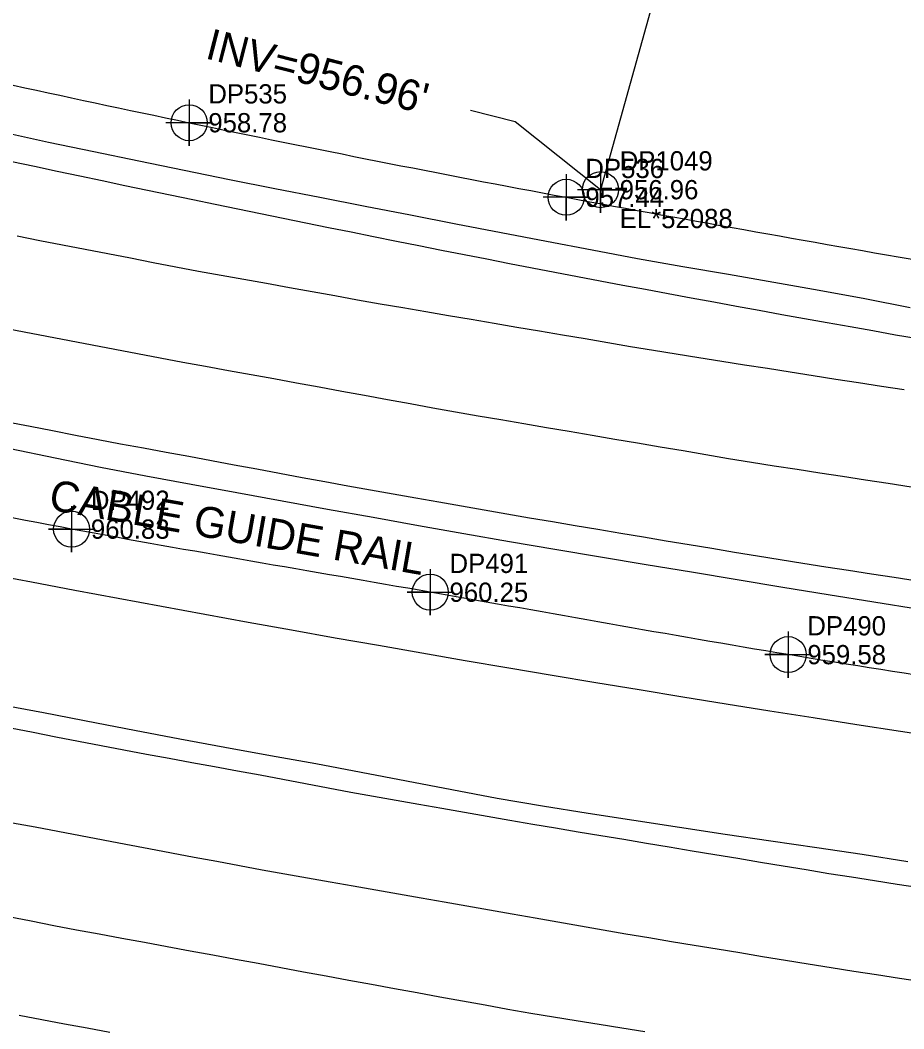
# Model space of a CAD drawing. Extents: x 1182322 to 1186765, y 572295 to 575411.
# Drawn here: x 1185843 to 1185957.8, y 573689.5 to 573820.6 of the extents above; entities that cross this region are included whole.
import ezdxf

# ---------------------------------------------------------------- set-up
doc = ezdxf.new("R2010")
doc.units = 0
for name, color, linetype in [('COGO Default Chain', 7, 'Continuous'), ('Exist Guardrail', 7, 'Continuous'), ('Exist Guardrail Cable Guide Rail', 7, 'Continuous'), ('Exist Guardrail Cable Guide Rail Cogo Elevation', 7, 'Continuous'), ('Exist Guardrail Cable Guide Rail Cogo Number', 7, 'Continuous'), ('Exist Guardrail Cable Guide Rail Cogo Point CELL', 7, 'Continuous'), ('Exist Guardrail Cable Guide Rail Text', 7, 'Continuous'), ('Exist Guardrail Cogo Elevation', 7, 'Continuous'), ('Exist Guardrail Cogo Number', 7, 'Continuous'), ('Exist Guardrail Cogo Point CELL', 7, 'Continuous'), ('Exist Horizontal Alignment', 7, 'Continuous'), ('Exist Roads EOP', 7, 'Continuous'), ('Exist Roads EOT', 7, 'Continuous'), ('Exist Structure Minor Pipes CMP 8 Inch', 7, 'Continuous'), ('Exist Structure Minor Pipes CMP 8 Inch Cogo Comment', 7, 'Continuous'), ('Exist Structure Minor Pipes CMP 8 Inch Cogo Elevation', 7, 'Continuous'), ('Exist Structure Minor Pipes CMP 8 Inch Cogo Number', 7, 'Continuous'), ('Exist Structure Minor Pipes CMP 8 Inch Cogo Point CELL', 7, 'Continuous'), ('Exist Structure Minor Pipes CMP 8 Inch Invert', 7, 'Continuous'), ('Exist Structure Minor Pipes CMP 8 Inch Leader', 7, 'Continuous')]:
    doc.layers.add(name, color=color, linetype=linetype)

msp = doc.modelspace()

# ---------------------------------------------------------------- linework, layer by layer
at = {"layer": 'COGO Default Chain'}
msp.add_arc((1186442.72, 576894.22), 3203, 256.26372, 262.82154, dxfattribs=at)
at = {"layer": 'Exist Guardrail'}
for points in [[(1185390.3, 573940.07), (1185437.01, 573922.28), (1185484.33, 573906.54), (1185526.22, 573893.43), (1185574.13, 573879.46), (1185622.33, 573866.54), (1185670.88, 573853.88), (1185719.13, 573841.46), (1185767.43, 573829.33), (1185816.18, 573817.9), (1185864.94, 573807.26), (1185913.93, 573797.57), (1185963.25, 573788.74), (1186012.41, 573780.34), (1186049.41, 573774.82)], [(1186024.1, 573651.4), (1185974.53, 573658.23), (1185925.08, 573665.96), (1185876.03, 573674.4), (1185826.75, 573683.69), (1185777.99, 573693.31), (1185734.89, 573702.52), (1185686.39, 573713.51)]]:
    msp.add_spline(points, degree=3, dxfattribs=at)
at = {"layer": 'Exist Guardrail Cable Guide Rail'}
msp.add_spline([(1186038.69, 573724.46), (1185991.11, 573730.82), (1185942.77, 573738.14), (1185896.28, 573746.25), (1185849.68, 573754.45), (1185801.69, 573764.04), (1185755.31, 573774.06), (1185708.64, 573784.68), (1185661.69, 573796.05), (1185615.35, 573807.21)], degree=3, dxfattribs=at)
at = {"layer": 'Exist Guardrail Cable Guide Rail Cogo Point CELL'}
for points in [[(1185849.68, 573757.45), (1185849.68, 573751.45), (1185849.68, 573754.45), (1185846.68, 573754.45), (1185852.68, 573754.45)], [(1185896.28, 573749.25), (1185896.28, 573743.25), (1185896.28, 573746.25), (1185893.28, 573746.25), (1185899.28, 573746.25)], [(1185942.77, 573741.14), (1185942.77, 573735.14), (1185942.77, 573738.14), (1185939.77, 573738.14), (1185945.77, 573738.14)]]:
    msp.add_lwpolyline(points, dxfattribs=at)
for centre in [(1185849.68, 573754.45), (1185896.28, 573746.25), (1185942.77, 573738.14)]:
    msp.add_circle(centre, 2.34, dxfattribs=at)
at = {"layer": 'Exist Guardrail Cogo Point CELL'}
for points in [[(1185864.94, 573810.26), (1185864.94, 573804.26), (1185864.94, 573807.26), (1185867.94, 573807.26), (1185861.94, 573807.26)], [(1185913.93, 573800.57), (1185913.93, 573794.57), (1185913.93, 573797.57), (1185916.93, 573797.57), (1185910.93, 573797.57)]]:
    msp.add_lwpolyline(points, dxfattribs=at)
for centre in [(1185864.94, 573807.26), (1185913.93, 573797.57)]:
    msp.add_circle(centre, 2.34, dxfattribs=at)
at = {"layer": 'Exist Horizontal Alignment'}
msp.add_arc((1186442.72, 576894.22), 3203, 256.26372, 262.82154, dxfattribs=at)
at = {"layer": 'Exist Roads EOP'}
for points in [[(1185840.82, 573806.03), (1185846.68, 573804.73), (1185852.55, 573803.51), (1185858.43, 573802.29), (1185864.3, 573801.08), (1185870.18, 573799.86), (1185876.06, 573798.71), (1185881.95, 573797.57), (1185887.84, 573796.42), (1185893.73, 573795.28), (1185899.62, 573794.14), (1185905.51, 573793), (1185911.4, 573791.87), (1185917.3, 573790.74), (1185923.19, 573789.62), (1185929.1, 573788.58), (1185935.01, 573787.56), (1185940.92, 573786.53), (1185946.83, 573785.51), (1185952.73, 573784.42), (1185958.62, 573783.27)], [(1185959.84, 573744.02), (1185953.91, 573744.97), (1185947.99, 573745.92), (1185942.07, 573746.88), (1185936.15, 573747.85), (1185930.23, 573748.84), (1185924.31, 573749.82), (1185918.39, 573750.81), (1185912.48, 573751.79), (1185906.56, 573752.79), (1185900.65, 573753.83), (1185894.75, 573754.89), (1185888.84, 573755.94), (1185882.93, 573757), (1185877.03, 573758.07), (1185871.13, 573759.16), (1185865.23, 573760.25), (1185859.33, 573761.34), (1185853.44, 573762.46), (1185847.56, 573763.67), (1185841.69, 573764.88)], [(1185840.13, 573731.72), (1185846.04, 573730.64), (1185852.92, 573729.28), (1185857.84, 573728.33), (1185863.74, 573727.18), (1185869.59, 573726.12), (1185875.5, 573725.05), (1185881.4, 573723.98), (1185887.3, 573722.88), (1185893.19, 573721.76), (1185899.08, 573720.63), (1185904.98, 573719.51), (1185910.87, 573718.49), (1185916.81, 573717.56), (1185922.72, 573716.63), (1185928.65, 573715.7), (1185934.59, 573714.8), (1185940.54, 573713.95), (1185946.49, 573713.09), (1185952.38, 573712.21), (1185958.32, 573711.24)]]:
    msp.add_lwpolyline(points, dxfattribs=at)
at = {"layer": 'Exist Roads EOT'}
for points in [[(1185841.93, 573802.24), (1185844.86, 573801.61), (1185847.79, 573800.98), (1185850.73, 573800.35), (1185853.66, 573799.74), (1185856.6, 573799.12), (1185859.54, 573798.5), (1185862.47, 573797.89), (1185865.41, 573797.29), (1185868.35, 573796.68), (1185871.29, 573796.07), (1185874.23, 573795.47), (1185877.16, 573794.86), (1185880.1, 573794.26), (1185883.04, 573793.66), (1185885.98, 573793.07), (1185888.92, 573792.47), (1185891.87, 573791.88), (1185894.81, 573791.3), (1185897.75, 573790.71), (1185900.69, 573790.13), (1185903.64, 573789.56), (1185906.58, 573788.98), (1185909.53, 573788.41), (1185912.47, 573787.85), (1185915.42, 573787.29), (1185918.37, 573786.73), (1185921.32, 573786.17), (1185924.26, 573785.62), (1185927.21, 573785.06), (1185930.16, 573784.51), (1185933.11, 573783.97), (1185936.06, 573783.43), (1185939.02, 573782.9), (1185941.97, 573782.36), (1185944.92, 573781.83), (1185947.87, 573781.3), (1185950.83, 573780.77), (1185953.78, 573780.24), (1185956.73, 573779.71), (1185959.69, 573779.2)], [(1185842.59, 573792.54), (1185845.54, 573791.97), (1185848.48, 573791.4), (1185851.43, 573790.83), (1185854.37, 573790.26), (1185857.32, 573789.69), (1185860.26, 573789.11), (1185863.21, 573788.55), (1185866.16, 573787.99), (1185869.11, 573787.45), (1185872.06, 573786.92), (1185875.01, 573786.39), (1185877.97, 573785.86), (1185880.92, 573785.33), (1185883.87, 573784.8), (1185886.82, 573784.26), (1185889.78, 573783.74), (1185892.73, 573783.23), (1185895.69, 573782.72), (1185898.65, 573782.22), (1185901.61, 573781.72), (1185904.56, 573781.21), (1185907.52, 573780.71), (1185910.48, 573780.2), (1185913.44, 573779.7), (1185916.39, 573779.2), (1185919.35, 573778.69), (1185922.31, 573778.19), (1185925.27, 573777.7), (1185928.23, 573777.23), (1185931.19, 573776.76), (1185934.16, 573776.29), (1185937.12, 573775.82), (1185940.08, 573775.35), (1185943.05, 573774.88), (1185946.01, 573774.41), (1185948.97, 573773.94), (1185951.94, 573773.49), (1185954.9, 573773.04), (1185957.87, 573772.6)], [(1185958.76, 573759.91), (1185955.79, 573760.37), (1185952.82, 573760.82), (1185949.86, 573761.27), (1185946.89, 573761.73), (1185943.93, 573762.18), (1185940.96, 573762.63), (1185938, 573763.11), (1185935.04, 573763.6), (1185932.08, 573764.1), (1185929.13, 573764.61), (1185926.17, 573765.11), (1185923.21, 573765.61), (1185920.25, 573766.11), (1185917.3, 573766.62), (1185914.34, 573767.12), (1185911.38, 573767.62), (1185908.42, 573768.12), (1185905.46, 573768.63), (1185902.51, 573769.13), (1185899.55, 573769.65), (1185896.6, 573770.18), (1185893.65, 573770.72), (1185890.7, 573771.26), (1185887.75, 573771.8), (1185884.8, 573772.34), (1185881.84, 573772.88), (1185878.89, 573773.42), (1185875.94, 573773.96), (1185872.99, 573774.5), (1185870.04, 573775.04), (1185867.09, 573775.58), (1185864.14, 573776.12), (1185861.19, 573776.68), (1185858.24, 573777.24), (1185855.3, 573777.8), (1185852.35, 573778.37), (1185849.4, 573778.93), (1185846.46, 573779.5), (1185843.51, 573780.06), (1185840.57, 573780.62)], [(1185841.32, 573768.38), (1185844.27, 573767.82), (1185847.21, 573767.25), (1185850.16, 573766.68), (1185853.11, 573766.11), (1185856.05, 573765.55), (1185859, 573765.01), (1185861.95, 573764.46), (1185864.9, 573763.91), (1185867.85, 573763.36), (1185870.8, 573762.81), (1185873.75, 573762.27), (1185876.7, 573761.72), (1185879.65, 573761.17), (1185882.6, 573760.63), (1185885.55, 573760.09), (1185888.5, 573759.56), (1185891.46, 573759.03), (1185894.41, 573758.5), (1185897.37, 573757.98), (1185900.32, 573757.46), (1185903.27, 573756.94), (1185906.23, 573756.43), (1185909.19, 573755.93), (1185912.15, 573755.43), (1185915.1, 573754.93), (1185918.06, 573754.43), (1185921.02, 573753.93), (1185923.98, 573753.43), (1185926.94, 573752.94), (1185929.9, 573752.45), (1185932.86, 573751.96), (1185935.82, 573751.47), (1185938.78, 573750.99), (1185941.74, 573750.51), (1185944.7, 573750.04), (1185947.67, 573749.57), (1185950.63, 573749.11), (1185953.59, 573748.65), (1185956.56, 573748.19), (1185959.53, 573747.74)], [(1185841.73, 573728.62), (1185844.67, 573728.05), (1185847.62, 573727.48), (1185850.57, 573726.91), (1185853.51, 573726.34), (1185856.46, 573725.77), (1185859.41, 573725.22), (1185862.36, 573724.68), (1185865.31, 573724.14), (1185868.26, 573723.59), (1185871.21, 573723.05), (1185874.16, 573722.51), (1185877.11, 573721.96), (1185880.06, 573721.41), (1185883, 573720.85), (1185885.95, 573720.29), (1185888.9, 573719.74), (1185891.86, 573719.23), (1185894.81, 573718.71), (1185897.77, 573718.2), (1185900.72, 573717.68), (1185903.68, 573717.16), (1185906.63, 573716.64), (1185909.59, 573716.13), (1185912.55, 573715.63), (1185915.5, 573715.13), (1185918.46, 573714.63), (1185921.42, 573714.14), (1185924.38, 573713.65), (1185927.34, 573713.15), (1185930.3, 573712.66), (1185933.26, 573712.17), (1185936.22, 573711.68), (1185939.18, 573711.19), (1185942.14, 573710.7), (1185945.1, 573710.21), (1185948.06, 573709.72), (1185951.02, 573709.26), (1185953.99, 573708.8), (1185956.95, 573708.33), (1185959.91, 573707.87)], [(1185960.21, 573695.64), (1185957.24, 573696.07), (1185954.27, 573696.51), (1185951.31, 573696.97), (1185948.35, 573697.45), (1185945.39, 573697.93), (1185942.42, 573698.41), (1185939.46, 573698.89), (1185936.5, 573699.37), (1185933.54, 573699.86), (1185930.58, 573700.34), (1185927.62, 573700.83), (1185924.66, 573701.32), (1185921.7, 573701.82), (1185918.75, 573702.33), (1185915.79, 573702.85), (1185912.84, 573703.37), (1185909.89, 573703.9), (1185906.93, 573704.42), (1185903.98, 573704.94), (1185901.02, 573705.46), (1185898.07, 573705.98), (1185895.11, 573706.49), (1185892.16, 573707.01), (1185889.2, 573707.53), (1185886.25, 573708.04), (1185883.29, 573708.56), (1185880.34, 573709.08), (1185877.38, 573709.61), (1185874.43, 573710.14), (1185871.48, 573710.69), (1185868.53, 573711.25), (1185865.59, 573711.8), (1185862.64, 573712.36), (1185859.69, 573712.92), (1185856.74, 573713.47), (1185853.79, 573714.03), (1185850.85, 573714.58), (1185847.9, 573715.14), (1185844.95, 573715.7), (1185842, 573716.25)], [(1185841.48, 573704.1), (1185844.42, 573703.53), (1185847.37, 573702.96), (1185850.31, 573702.4), (1185853.26, 573701.85), (1185856.21, 573701.3), (1185859.16, 573700.76), (1185862.11, 573700.21), (1185865.06, 573699.66), (1185868.01, 573699.12), (1185870.96, 573698.57), (1185873.91, 573698.03), (1185876.86, 573697.48), (1185879.81, 573696.93), (1185882.76, 573696.39), (1185885.71, 573695.84), (1185888.66, 573695.3), (1185891.61, 573694.75), (1185894.56, 573694.22), (1185897.52, 573693.68), (1185900.47, 573693.15), (1185903.42, 573692.62), (1185906.37, 573692.08), (1185909.33, 573691.57), (1185912.29, 573691.09), (1185915.25, 573690.61), (1185918.21, 573690.13), (1185921.17, 573689.65), (1185924.14, 573689.17)], [(1185854.66, 573689.02), (1185851.71, 573689.58), (1185848.76, 573690.14), (1185845.81, 573690.7), (1185842.86, 573691.23)]]:
    msp.add_lwpolyline(points, dxfattribs=at)
at = {"layer": 'Exist Structure Minor Pipes CMP 8 Inch'}
msp.add_line((1185930.63, 573842.39), (1185918.39, 573798.56), dxfattribs=at)
at = {"layer": 'Exist Structure Minor Pipes CMP 8 Inch Cogo Point CELL'}
msp.add_lwpolyline([(1185918.39, 573801.56), (1185918.39, 573795.56), (1185918.39, 573798.56), (1185921.39, 573798.56), (1185915.39, 573798.56)], dxfattribs=at)
msp.add_circle((1185918.39, 573798.56), 2.34, dxfattribs=at)
at = {"layer": 'Exist Structure Minor Pipes CMP 8 Inch Leader'}
msp.add_lwpolyline([(1185918.39, 573798.56), (1185907.3, 573807.38), (1185901.49, 573808.86)], dxfattribs=at)

# ---------------------------------------------------------------- texts
at = {"layer": 'Exist Guardrail Cable Guide Rail Cogo Elevation'}
for s, p in [('960.83', (1185852.18, 573753.2)), ('960.25', (1185898.78, 573745)), ('959.58', (1185945.27, 573736.89))]:
    msp.add_text(s, height=2.5, dxfattribs=at).set_placement(p)
at = {"layer": 'Exist Guardrail Cable Guide Rail Cogo Number'}
for s, p in [('DP492', (1185852.18, 573756.95)), ('DP491', (1185898.78, 573748.75)), ('DP490', (1185945.27, 573740.64))]:
    msp.add_text(s, height=2.5, dxfattribs=at).set_placement(p)
at = {"layer": 'Exist Guardrail Cable Guide Rail Text'}
msp.add_text('CABLE GUIDE RAIL', height=4, rotation=350.0386, dxfattribs=at).set_placement((1185846.57, 573757))
at = {"layer": 'Exist Guardrail Cogo Elevation'}
for s, p in [('958.78', (1185867.44, 573806.01)), ('957.44', (1185916.43, 573796.32))]:
    msp.add_text(s, height=2.5, dxfattribs=at).set_placement(p)
at = {"layer": 'Exist Guardrail Cogo Number'}
for s, p in [('DP535', (1185867.44, 573809.76)), ('DP536', (1185916.43, 573800.07))]:
    msp.add_text(s, height=2.5, dxfattribs=at).set_placement(p)
at = {"layer": 'Exist Structure Minor Pipes CMP 8 Inch Cogo Comment'}
msp.add_text('EL*52088', height=2.5, dxfattribs=at).set_placement((1185920.89, 573793.56))
at = {"layer": 'Exist Structure Minor Pipes CMP 8 Inch Cogo Elevation'}
msp.add_text('956.96', height=2.5, dxfattribs=at).set_placement((1185920.89, 573797.31))
at = {"layer": 'Exist Structure Minor Pipes CMP 8 Inch Cogo Number'}
msp.add_text('DP1049', height=2.5, dxfattribs=at).set_placement((1185920.89, 573801.06))
at = {"layer": 'Exist Structure Minor Pipes CMP 8 Inch Invert'}
msp.add_text("INV=956.96'", height=4, rotation=345.6405, dxfattribs=at).set_placement((1185866.9, 573815.66))

doc.saveas('drawing.dxf')
